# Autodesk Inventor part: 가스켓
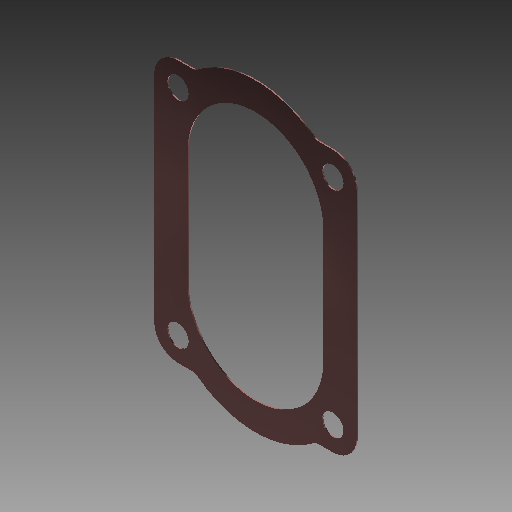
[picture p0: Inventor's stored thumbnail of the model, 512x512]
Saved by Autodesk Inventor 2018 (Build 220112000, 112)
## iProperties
Created: 2023-05
Part Number: 가스켓
Material: 스테인리스강
Document SubType Name: Modeling
Designer: mdu-01
Density: 1 g/cm^3
Appearance: 반광택(1)
Author: mdu-01
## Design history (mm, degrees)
sketch "스케치1"
  geometry: L1 (-42.5, 45)-(-42.5, -45) reference; L2 (-32.5, -55)-(-26.325, -55) reference; L3 (26.325, -55)-(32.5, -55) reference; L4 (42.5, -45)-(42.5, 45) reference; L5 (32.5, 55)-(26.325, 55) reference; L6 (-26.325, 55)-(-32.5, 55) reference; L7 (-28.5, -24)-(-28.5, 24) reference; L8 (28.5, 24)-(28.5, -24) reference; C1 r 4.5 at (32.5, -45) reference; C2 r 4.5 at (-32.5, 45) reference; C3 r 4.5 at (32.5, 45) reference; C4 r 4.5 at (-32.5, -45) reference; A1 r 10 centre (-32.5, -45) between (-42.5, -45) and (-32.5, -55) reference; A2 r 3 centre (-26.325, -58) between (-24.488, -55.628) and (-26.325, -55) reference; A3 r 40 centre (0, -24) between (-24.488, -55.628) and (24.488, -55.628) reference; A4 r 3 centre (26.325, -58) between (26.325, -55) and (24.488, -55.628) reference; A5 r 10 centre (32.5, -45) between (32.5, -55) and (42.5, -45) reference; A6 r 10 centre (32.5, 45) between (42.5, 45) and (32.5, 55) reference; A7 r 3 centre (26.325, 58) between (24.488, 55.628) and (26.325, 55) reference; A8 r 40 centre (0, 24) between (24.488, 55.628) and (-24.488, 55.628) reference; A9 r 3 centre (-26.325, 58) between (-26.325, 55) and (-24.488, 55.628) reference; A10 r 10 centre (-32.5, 45) between (-32.5, 55) and (-42.5, 45) reference; A11 r 28.5 centre (0, 24) between (28.5, 24) and (-28.5, 24) reference; A12 r 28.5 centre (0, -24) between (-28.5, -24) and (28.5, -24) reference; 1 further point
extrude "돌출1" new body sketch "스케치1" distance "d0" = 0.5; taper "d1" = 0 deg
node "솔리드1"
node "참조1"
